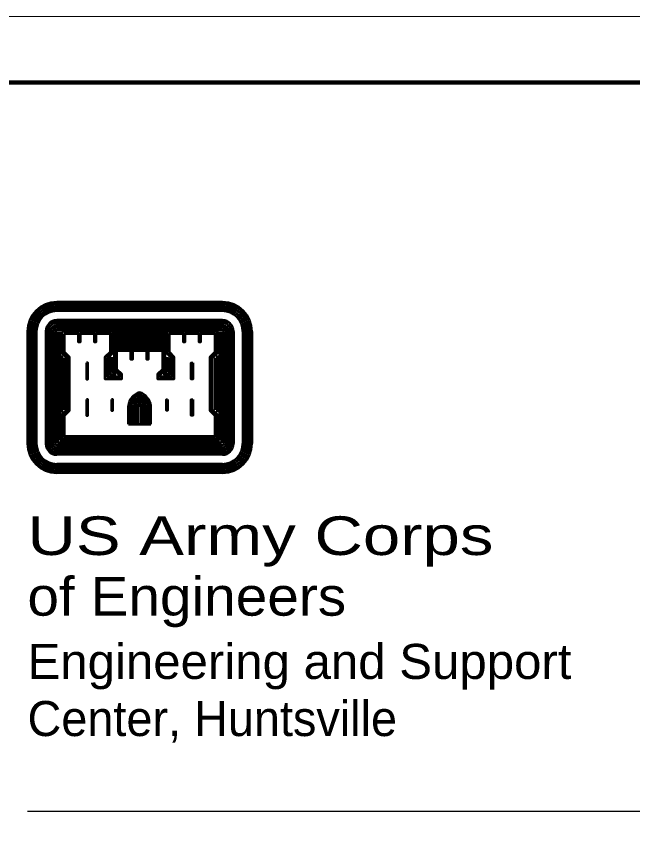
# Model space of a CAD drawing. Extents: x -153.1 to -120, y 360.9 to 384.2.
# Drawn here: x -149.62 to -145.22, y 378.39 to 384.24 of the extents above; entities that cross this region are included whole.
import ezdxf

# ---------------------------------------------------------------- set-up
doc = ezdxf.new("R2010")
doc.units = 0
doc.header["$LTSCALE"] = 0.039
doc.layers.add('1', color=7, linetype='Continuous', lineweight=80)
doc.layers.add('2', color=7, linetype='Continuous', lineweight=53)

msp = doc.modelspace()

# ---------------------------------------------------------------- linework, layer by layer
at = {"layer": '1', "lineweight": 25}
for p in [(-124.33602, 378.5668), (-126.54058, 378.5668)]:
    msp.add_line(p, (-149.54265, 378.5668), dxfattribs=at)
at = {"layer": '1', "lineweight": 13}
msp.add_lwpolyline([(-153.08523, 360.85466), (-119.97531, 360.85466), (-119.97531, 384.24028), (-153.08523, 384.24028)], close=True, dxfattribs=at)
msp.add_lwpolyline([(-153.08523, 360.85466), (-119.97531, 360.85466), (-119.97531, 384.24028), (-153.08523, 384.24028)], close=True, dxfattribs=at)
msp.add_lwpolyline([(-153.08523, 360.85466), (-119.97531, 360.85466), (-119.97531, 384.24028), (-153.08523, 384.24028)], close=True, dxfattribs=at)
at = {"layer": '1', "lineweight": 90}
msp.add_lwpolyline([(-152.02225, 383.76784), (-120.44775, 383.76784), (-120.44775, 361.32709)], dxfattribs=at)
msp.add_lwpolyline([(-152.02225, 383.76784), (-120.44775, 383.76784), (-120.44775, 361.32709)], dxfattribs=at)
msp.add_lwpolyline([(-152.02225, 383.76784), (-120.44775, 383.76784), (-120.44775, 361.32709)], dxfattribs=at)
at = {"layer": '2'}
for p, q in [((-148.14948, 382.20126), (-149.33242, 382.20126)), ((-148.14948, 382.20126), (-149.33242, 382.20126)), ((-148.14948, 382.20126), (-149.33242, 382.20126)), ((-148.14948, 382.18874), (-149.33242, 382.18874)), ((-148.14948, 382.18874), (-149.33242, 382.18874)), ((-148.14948, 382.18874), (-149.33242, 382.18874)), ((-148.14948, 382.17172), (-149.33242, 382.17172)), ((-148.14948, 382.17172), (-149.33242, 382.17172)), ((-148.14948, 382.17172), (-149.33242, 382.17172)), ((-148.14948, 382.15503), (-149.33242, 382.15503)), ((-148.14948, 382.15503), (-149.33242, 382.15503)), ((-148.14948, 382.15503), (-149.33242, 382.15503)), ((-148.14948, 382.13864), (-149.33242, 382.13864)), ((-148.14948, 382.13864), (-149.33242, 382.13864)), ((-148.14948, 382.13864), (-149.33242, 382.13864)), ((-148.14948, 382.07149), (-149.33242, 382.07149)), ((-148.14948, 382.07149), (-149.33242, 382.07149)), ((-148.14948, 382.07149), (-149.33242, 382.07149)), ((-148.14948, 382.05255), (-149.33242, 382.05255)), ((-148.14948, 382.05255), (-149.33242, 382.05255)), ((-148.14948, 382.05255), (-149.33242, 382.05255)), ((-148.14948, 382.03639), (-149.33242, 382.03639)), ((-148.14948, 382.03639), (-149.33242, 382.03639)), ((-148.14948, 382.03639), (-149.33242, 382.03639)), ((-148.14948, 382.01966), (-149.33242, 382.01966)), ((-148.14948, 382.01966), (-149.33242, 382.01966)), ((-148.14948, 382.01966), (-149.33242, 382.01966)), ((-149.54265, 381.99128), (-149.54265, 381.19178)), ((-149.54265, 381.99128), (-149.54265, 381.19178)), ((-149.54265, 381.99128), (-149.54265, 381.19178)), ((-149.53042, 381.99128), (-149.53042, 381.19178)), ((-149.53042, 381.99128), (-149.53042, 381.19178)), ((-149.51177, 381.99128), (-149.51177, 381.19178)), ((-149.51177, 381.99128), (-149.51177, 381.19178)), ((-149.49531, 381.99128), (-149.49531, 381.19178)), ((-149.49531, 381.99128), (-149.49531, 381.19178)), ((-149.47917, 381.99128), (-149.47917, 381.19178)), ((-149.47917, 381.99128), (-149.47917, 381.19178)), ((-149.4101, 381.99128), (-149.4101, 381.19178)), ((-149.4101, 381.99128), (-149.4101, 381.19178)), ((-149.4101, 381.99128), (-149.4101, 381.19178)), ((-149.39479, 381.99128), (-149.39479, 381.19178)), ((-149.39479, 381.99128), (-149.39479, 381.19178)), ((-149.39479, 381.99128), (-149.39479, 381.19178)), ((-149.37721, 381.99128), (-149.37721, 381.19178)), ((-149.37721, 381.99128), (-149.37721, 381.19178)), ((-149.37721, 381.99128), (-149.37721, 381.19178)), ((-149.35998, 381.99128), (-149.35998, 381.19178)), ((-149.35998, 381.99128), (-149.35998, 381.19178)), ((-149.35998, 381.99128), (-149.35998, 381.19178)), ((-149.34325, 381.99128), (-149.34325, 381.19178)), ((-149.34325, 381.99128), (-149.34325, 381.19178)), ((-149.34325, 381.99128), (-149.34325, 381.19178)), ((-148.14948, 382.00243), (-149.33242, 382.00243)), ((-148.14948, 382.00243), (-149.33242, 382.00243)), ((-148.14948, 382.00243), (-149.33242, 382.00243)), ((-149.32708, 381.99128), (-149.32708, 381.19791)), ((-149.32708, 381.99128), (-149.32708, 381.19791)), ((-149.30988, 381.99128), (-149.30988, 381.2152)), ((-149.30988, 381.99128), (-149.30988, 381.2152)), ((-148.92358, 381.98709), (-148.55933, 381.98709)), ((-148.92358, 381.98709), (-148.55933, 381.98709)), ((-148.92358, 381.97066), (-148.55933, 381.97066)), ((-148.92358, 381.97066), (-148.55933, 381.97066)), ((-148.92358, 381.95453), (-148.55933, 381.95453)), ((-148.92358, 381.95453), (-148.55933, 381.95453)), ((-148.17204, 381.99128), (-148.17204, 381.2152)), ((-148.17204, 381.99128), (-148.17204, 381.2152)), ((-148.15583, 381.99128), (-148.15583, 381.19791)), ((-148.15583, 381.99128), (-148.15583, 381.19791)), ((-148.13915, 381.99128), (-148.13915, 381.19178)), ((-148.13915, 381.99128), (-148.13915, 381.19178)), ((-148.13915, 381.99128), (-148.13915, 381.19178)), ((-148.12077, 381.99128), (-148.12077, 381.19178)), ((-148.12077, 381.99128), (-148.12077, 381.19178)), ((-148.12077, 381.99128), (-148.12077, 381.19178)), ((-148.10519, 381.99128), (-148.10519, 381.19178)), ((-148.10519, 381.99128), (-148.10519, 381.19178)), ((-148.10519, 381.99128), (-148.10519, 381.19178)), ((-148.08904, 381.99128), (-148.08904, 381.19178)), ((-148.08904, 381.99128), (-148.08904, 381.19178)), ((-148.08904, 381.99128), (-148.08904, 381.19178)), ((-148.07067, 381.99128), (-148.07067, 381.19178)), ((-148.07067, 381.99128), (-148.07067, 381.19178)), ((-148.07067, 381.99128), (-148.07067, 381.19178)), ((-148.00381, 381.99128), (-148.00381, 381.19178)), ((-148.00381, 381.99128), (-148.00381, 381.19178)), ((-148.00381, 381.99128), (-148.00381, 381.19178)), ((-147.98656, 381.99128), (-147.98656, 381.19178)), ((-147.98656, 381.99128), (-147.98656, 381.19178)), ((-147.98656, 381.99128), (-147.98656, 381.19178)), ((-147.969, 381.99128), (-147.969, 381.19178)), ((-147.969, 381.99128), (-147.969, 381.19178)), ((-147.95288, 381.99128), (-147.95288, 381.19178)), ((-147.95288, 381.99128), (-147.95288, 381.19178)), ((-147.94033, 381.99128), (-147.94033, 381.19178)), ((-147.94033, 381.99128), (-147.94033, 381.19178)), ((-147.94033, 381.99128), (-147.94033, 381.19178)), ((-148.92358, 381.93699), (-148.55933, 381.93699)), ((-148.92358, 381.93699), (-148.55933, 381.93699)), ((-148.92358, 381.92053), (-148.55933, 381.92053)), ((-148.92358, 381.92053), (-148.55933, 381.92053)), ((-148.92358, 381.90355), (-148.55933, 381.90355)), ((-148.92358, 381.90355), (-148.55933, 381.90355)), ((-148.92358, 381.88547), (-148.55933, 381.88547)), ((-148.92358, 381.88547), (-148.55933, 381.88547)), ((-149.29704, 381.82084), (-149.29704, 381.41234)), ((-149.29704, 381.82084), (-149.29704, 381.41234)), ((-149.27867, 381.80416), (-149.27867, 381.43186)), ((-149.27867, 381.80416), (-149.27867, 381.43186)), ((-148.2021, 381.80416), (-148.2021, 381.43186)), ((-148.2021, 381.80416), (-148.2021, 381.43186)), ((-148.18708, 381.81949), (-148.18708, 381.41484)), ((-148.18708, 381.81949), (-148.18708, 381.41484)), ((-148.82004, 381.33074), (-148.82004, 381.46109)), ((-148.82004, 381.33074), (-148.82004, 381.46109)), ((-148.80335, 381.33074), (-148.80335, 381.46109)), ((-148.80335, 381.33074), (-148.80335, 381.46109)), ((-148.78604, 381.33074), (-148.78604, 381.46109)), ((-148.78604, 381.33074), (-148.78604, 381.46109)), ((-148.76994, 381.33074), (-148.76994, 381.46109)), ((-148.76994, 381.33074), (-148.76994, 381.46109)), ((-148.75098, 381.33074), (-148.75098, 381.46109)), ((-148.75098, 381.33074), (-148.75098, 381.46109)), ((-148.72977, 381.33074), (-148.72977, 381.46109)), ((-148.72977, 381.33074), (-148.72977, 381.46109)), ((-148.71337, 381.33074), (-148.71337, 381.46109)), ((-148.71337, 381.33074), (-148.71337, 381.46109)), ((-148.69583, 381.33074), (-148.69583, 381.46109)), ((-148.69583, 381.33074), (-148.69583, 381.46109)), ((-148.67967, 381.33074), (-148.67967, 381.46109)), ((-148.67967, 381.33074), (-148.67967, 381.46109)), ((-148.6621, 381.33074), (-148.6621, 381.46109)), ((-148.6621, 381.33074), (-148.6621, 381.46109)), ((-148.82004, 381.33074), (-148.6621, 381.33074)), ((-148.82004, 381.33074), (-148.6621, 381.33074)), ((-148.15583, 381.19791), (-149.32708, 381.19791)), ((-148.15583, 381.19791), (-149.32708, 381.19791)), ((-148.17204, 381.2152), (-149.30988, 381.2152)), ((-148.17204, 381.2152), (-149.30988, 381.2152)), ((-148.14948, 381.18039), (-149.33242, 381.18039)), ((-148.14948, 381.18039), (-149.33242, 381.18039)), ((-148.14948, 381.18039), (-149.33242, 381.18039)), ((-148.14948, 381.16424), (-149.33242, 381.16424)), ((-148.14948, 381.16424), (-149.33242, 381.16424)), ((-148.14948, 381.16424), (-149.33242, 381.16424)), ((-148.14948, 381.14668), (-149.33242, 381.14668)), ((-148.14948, 381.14668), (-149.33242, 381.14668)), ((-148.14948, 381.14668), (-149.33242, 381.14668)), ((-148.14948, 381.12999), (-149.33242, 381.12999)), ((-148.14948, 381.12999), (-149.33242, 381.12999)), ((-148.14948, 381.12999), (-149.33242, 381.12999)), ((-148.14948, 381.11272), (-149.33242, 381.11272)), ((-148.14948, 381.11272), (-149.33242, 381.11272)), ((-148.14948, 381.11272), (-149.33242, 381.11272)), ((-148.14948, 381.04476), (-149.33242, 381.04476)), ((-148.14948, 381.04476), (-149.33242, 381.04476)), ((-148.14948, 381.02836), (-149.33242, 381.02836)), ((-148.14948, 381.02836), (-149.33242, 381.02836)), ((-148.14948, 381.01249), (-149.33242, 381.01249)), ((-148.14948, 381.01249), (-149.33242, 381.01249)), ((-148.14948, 380.99466), (-149.33242, 380.99466)), ((-148.14948, 380.99466), (-149.33242, 380.99466)), ((-148.14948, 380.98239), (-149.33242, 380.98239)), ((-148.14948, 380.98239), (-149.33242, 380.98239)), ((-148.14948, 380.98239), (-149.33242, 380.98239))]:
    msp.add_line(p, q, dxfattribs=at)
for points in [[(-149.29704, 381.99128), (-149.29704, 381.83926), (-149.26221, 381.80416), (-149.26221, 381.43186), (-149.29704, 381.39676), (-149.29704, 381.22772), (-148.18537, 381.22772), (-148.18537, 381.39676), (-148.22048, 381.43186), (-148.22048, 381.80416), (-148.18537, 381.83926), (-148.18537, 381.99128), (-148.33133, 381.99128), (-148.44606, 381.99128), (-148.54937, 381.99128), (-148.54937, 381.83926), (-148.51288, 381.80416), (-148.51288, 381.66911), (-148.59392, 381.66911), (-148.59392, 381.68166), (-148.55933, 381.71643), (-148.55933, 381.86849), (-148.70669, 381.86849), (-148.81865, 381.86849), (-148.92358, 381.86849), (-148.92358, 381.71643), (-148.88852, 381.68166), (-148.88852, 381.66911), (-148.96787, 381.66911), (-148.96787, 381.80416), (-148.93281, 381.83926), (-148.93281, 381.99128), (-149.08181, 381.99128), (-149.19427, 381.99128)], [(-149.29704, 381.99128), (-149.29704, 381.83926), (-149.26221, 381.80416), (-149.26221, 381.43186), (-149.29704, 381.39676), (-149.29704, 381.22772), (-148.18537, 381.22772), (-148.18537, 381.39676), (-148.22048, 381.43186), (-148.22048, 381.80416), (-148.18537, 381.83926), (-148.18537, 381.99128), (-148.33133, 381.99128), (-148.44606, 381.99128), (-148.54937, 381.99128), (-148.54937, 381.83926), (-148.51288, 381.80416), (-148.51288, 381.66911), (-148.59392, 381.66911), (-148.59392, 381.68166), (-148.55933, 381.71643), (-148.55933, 381.86849), (-148.70669, 381.86849), (-148.81865, 381.86849), (-148.92358, 381.86849), (-148.92358, 381.71643), (-148.88852, 381.68166), (-148.88852, 381.66911), (-148.96787, 381.66911), (-148.96787, 381.80416), (-148.93281, 381.83926), (-148.93281, 381.99128), (-149.08181, 381.99128), (-149.19427, 381.99128)], [(-149.29704, 381.99128), (-149.29704, 381.83926), (-149.26221, 381.80416), (-149.26221, 381.43186), (-149.29704, 381.39676), (-149.29704, 381.22772), (-148.18537, 381.22772), (-148.18537, 381.39676), (-148.22048, 381.43186), (-148.22048, 381.80416), (-148.18537, 381.83926), (-148.18537, 381.99128), (-148.33133, 381.99128), (-148.44606, 381.99128), (-148.54937, 381.99128), (-148.54937, 381.83926), (-148.51288, 381.80416), (-148.51288, 381.66911), (-148.59392, 381.66911), (-148.59392, 381.68166), (-148.55933, 381.71643), (-148.55933, 381.86849), (-148.70669, 381.86849), (-148.81865, 381.86849), (-148.92358, 381.86849), (-148.92358, 381.71643), (-148.88852, 381.68166), (-148.88852, 381.66911), (-148.96787, 381.66911), (-148.96787, 381.80416), (-148.93281, 381.83926), (-148.93281, 381.99128), (-149.08181, 381.99128), (-149.19427, 381.99128)], [(-149.27977, 381.97459), (-149.27977, 381.84536), (-149.24552, 381.81084), (-149.24552, 381.42572), (-149.27977, 381.39061), (-149.27977, 381.24526), (-148.2021, 381.24526), (-148.2021, 381.39061), (-148.23692, 381.42572), (-148.23692, 381.81084), (-148.2021, 381.84536), (-148.2021, 381.97459), (-148.30569, 381.97459), (-148.30569, 381.91443), (-148.31571, 381.91443), (-148.31571, 381.97459), (-148.41904, 381.97459), (-148.41904, 381.91443), (-148.42767, 381.91443), (-148.42767, 381.97459), (-148.53044, 381.97459), (-148.53044, 381.84536), (-148.49783, 381.81084), (-148.49783, 381.65155), (-148.6106, 381.65155), (-148.6106, 381.68916), (-148.57635, 381.72311), (-148.57635, 381.85345), (-148.67967, 381.85345), (-148.67967, 381.79159), (-148.68971, 381.79159), (-148.68971, 381.85345), (-148.79331, 381.85345), (-148.79331, 381.79159), (-148.80335, 381.79159), (-148.80335, 381.85345), (-148.90608, 381.85345), (-148.90608, 381.72311), (-148.87017, 381.68916), (-148.87017, 381.65155), (-148.98654, 381.65155), (-148.98654, 381.81084), (-148.95033, 381.84536), (-148.95033, 381.97459), (-149.0531, 381.97459), (-149.0531, 381.91443), (-149.06398, 381.91443), (-149.06398, 381.97459), (-149.16698, 381.97459), (-149.16698, 381.91443), (-149.17675, 381.91443), (-149.17675, 381.97459)], [(-149.27977, 381.97459), (-149.27977, 381.84536), (-149.24552, 381.81084), (-149.24552, 381.42572), (-149.27977, 381.39061), (-149.27977, 381.24526), (-148.2021, 381.24526), (-148.2021, 381.39061), (-148.23692, 381.42572), (-148.23692, 381.81084), (-148.2021, 381.84536), (-148.2021, 381.97459), (-148.30569, 381.97459), (-148.30569, 381.91443), (-148.31571, 381.91443), (-148.31571, 381.97459), (-148.41904, 381.97459), (-148.41904, 381.91443), (-148.42767, 381.91443), (-148.42767, 381.97459), (-148.53044, 381.97459), (-148.53044, 381.84536), (-148.49783, 381.81084), (-148.49783, 381.65155), (-148.6106, 381.65155), (-148.6106, 381.68916), (-148.57635, 381.72311), (-148.57635, 381.85345), (-148.67967, 381.85345), (-148.67967, 381.79159), (-148.68971, 381.79159), (-148.68971, 381.85345), (-148.79331, 381.85345), (-148.79331, 381.79159), (-148.80335, 381.79159), (-148.80335, 381.85345), (-148.90608, 381.85345), (-148.90608, 381.72311), (-148.87017, 381.68916), (-148.87017, 381.65155), (-148.98654, 381.65155), (-148.98654, 381.81084), (-148.95033, 381.84536), (-148.95033, 381.97459), (-149.0531, 381.97459), (-149.0531, 381.91443), (-149.06398, 381.91443), (-149.06398, 381.97459), (-149.16698, 381.97459), (-149.16698, 381.91443), (-149.17675, 381.91443), (-149.17675, 381.97459)], [(-149.27977, 381.97459), (-149.27977, 381.84536), (-149.24552, 381.81084), (-149.24552, 381.42572), (-149.27977, 381.39061), (-149.27977, 381.24526), (-148.2021, 381.24526), (-148.2021, 381.39061), (-148.23692, 381.42572), (-148.23692, 381.81084), (-148.2021, 381.84536), (-148.2021, 381.97459), (-148.30569, 381.97459), (-148.30569, 381.91443), (-148.31571, 381.91443), (-148.31571, 381.97459), (-148.41904, 381.97459), (-148.41904, 381.91443), (-148.42767, 381.91443), (-148.42767, 381.97459), (-148.53044, 381.97459), (-148.53044, 381.84536), (-148.49783, 381.81084), (-148.49783, 381.65155), (-148.6106, 381.65155), (-148.6106, 381.68916), (-148.57635, 381.72311), (-148.57635, 381.85345), (-148.67967, 381.85345), (-148.67967, 381.79159), (-148.68971, 381.79159), (-148.68971, 381.85345), (-148.79331, 381.85345), (-148.79331, 381.79159), (-148.80335, 381.79159), (-148.80335, 381.85345), (-148.90608, 381.85345), (-148.90608, 381.72311), (-148.87017, 381.68916), (-148.87017, 381.65155), (-148.98654, 381.65155), (-148.98654, 381.81084), (-148.95033, 381.84536), (-148.95033, 381.97459), (-149.0531, 381.97459), (-149.0531, 381.91443), (-149.06398, 381.91443), (-149.06398, 381.97459), (-149.16698, 381.97459), (-149.16698, 381.91443), (-149.17675, 381.91443), (-149.17675, 381.97459)], [(-149.12023, 381.76684), (-149.12023, 381.65155), (-149.11019, 381.65155), (-149.11019, 381.76684)], [(-149.12023, 381.76684), (-149.12023, 381.65155), (-149.11019, 381.65155), (-149.11019, 381.76684)], [(-148.36225, 381.76684), (-148.36225, 381.65155), (-148.3725, 381.65155), (-148.3725, 381.76684)], [(-148.36225, 381.76684), (-148.36225, 381.65155), (-148.3725, 381.65155), (-148.3725, 381.76684)], [(-149.12023, 381.50507), (-149.12023, 381.39172), (-149.11019, 381.39172), (-149.11019, 381.50507)], [(-149.12023, 381.50507), (-149.12023, 381.39172), (-149.11019, 381.39172), (-149.11019, 381.50507)], [(-148.94225, 381.50507), (-148.94225, 381.42686), (-148.9314, 381.42686), (-148.9314, 381.50507)], [(-148.94225, 381.50507), (-148.94225, 381.42686), (-148.9314, 381.42686), (-148.9314, 381.50507)], [(-148.54129, 381.50507), (-148.54129, 381.42686), (-148.55044, 381.42686), (-148.55044, 381.50507)], [(-148.54129, 381.50507), (-148.54129, 381.42686), (-148.55044, 381.42686), (-148.55044, 381.50507)], [(-148.36225, 381.50507), (-148.36225, 381.39172), (-148.3725, 381.39172), (-148.3725, 381.50507)], [(-148.36225, 381.50507), (-148.36225, 381.39172), (-148.3725, 381.39172), (-148.3725, 381.50507)]]:
    msp.add_lwpolyline(points, close=True, dxfattribs=at)
for points in [[(-148.94119, 381.80666), (-148.95144, 381.79666), (-148.95144, 381.68555), (-148.91527, 381.68555), (-148.93975, 381.71003), (-148.93975, 381.8078)], [(-148.94119, 381.80666), (-148.95144, 381.79666), (-148.95144, 381.68555), (-148.91527, 381.68555), (-148.93975, 381.71003), (-148.93975, 381.8078)], [(-148.54129, 381.80666), (-148.53044, 381.79666), (-148.53044, 381.68555), (-148.5655, 381.68555), (-148.54265, 381.71003), (-148.54265, 381.8078)], [(-148.54129, 381.80666), (-148.53044, 381.79666), (-148.53044, 381.68555), (-148.5655, 381.68555), (-148.54265, 381.71003), (-148.54265, 381.8078)]]:
    msp.add_lwpolyline(points, dxfattribs=at)
for centre, radius, start, end in [((-149.3329, 381.99206), 0.20886, 90, 180), ((-149.3329, 381.99206), 0.20886, 90, 180), ((-149.3329, 381.99206), 0.20886, 90, 180), ((-149.3329, 381.99206), 0.19678, 90, 180), ((-149.3329, 381.99206), 0.19678, 90, 180), ((-148.14935, 381.99206), 0.20886, 0, 90), ((-148.14935, 381.99206), 0.20886, 0, 90), ((-148.14935, 381.99206), 0.20886, 0, 90), ((-148.14935, 381.99206), 0.19678, 0, 90), ((-148.14935, 381.99206), 0.19678, 0, 90), ((-149.3329, 381.99206), 0.17985, 90, 180), ((-149.3329, 381.99206), 0.17985, 90, 180), ((-149.3329, 381.99206), 0.16293, 90, 180), ((-149.3329, 381.99206), 0.16293, 90, 180), ((-149.3329, 381.99206), 0.14601, 90, 180), ((-149.3329, 381.99206), 0.14601, 90, 180), ((-148.14935, 381.99206), 0.17985, 0, 90), ((-148.14935, 381.99206), 0.17985, 0, 90), ((-148.14935, 381.99206), 0.16293, 0, 90), ((-148.14935, 381.99206), 0.16293, 0, 90), ((-148.14935, 381.99206), 0.14601, 0, 90), ((-148.14935, 381.99206), 0.14601, 0, 90), ((-149.3329, 381.99206), 0.07832, 90, 180), ((-149.3329, 381.99206), 0.07832, 90, 180), ((-149.3329, 381.99206), 0.07832, 90, 180), ((-148.14935, 381.99206), 0.07832, 0, 90), ((-148.14935, 381.99206), 0.07832, 0, 90), ((-148.14935, 381.99206), 0.07832, 0, 90), ((-149.3329, 381.99206), 0.0614, 90, 180), ((-149.3329, 381.99206), 0.0614, 90, 180), ((-149.3329, 381.99206), 0.0614, 90, 180), ((-149.3329, 381.99206), 0.04448, 90, 180), ((-149.3329, 381.99206), 0.04448, 90, 180), ((-149.3329, 381.99206), 0.04448, 90, 180), ((-149.3329, 381.99206), 0.02756, 90, 180), ((-149.3329, 381.99206), 0.02756, 90, 180), ((-149.3329, 381.99206), 0.02756, 90, 180), ((-148.14935, 381.99206), 0.0614, 0, 90), ((-148.14935, 381.99206), 0.0614, 0, 90), ((-148.14935, 381.99206), 0.0614, 0, 90), ((-148.14935, 381.99206), 0.04448, 0, 90), ((-148.14935, 381.99206), 0.04448, 0, 90), ((-148.14935, 381.99206), 0.04448, 0, 90), ((-148.14935, 381.99206), 0.02756, 0, 90), ((-148.14935, 381.99206), 0.02756, 0, 90), ((-148.14935, 381.99206), 0.02756, 0, 90), ((-149.3329, 381.99206), 0.01064, 90, 180), ((-149.3329, 381.99206), 0.01064, 90, 180), ((-149.3329, 381.99206), 0.01064, 90, 180), ((-148.14935, 381.99206), 0.01064, 0, 90), ((-148.14935, 381.99206), 0.01064, 0, 90), ((-148.14935, 381.99206), 0.01064, 0, 90), ((-148.71197, 381.45259), 0.10826, 105.66806, 176.05748), ((-148.71197, 381.45259), 0.10826, 105.66806, 176.05748), ((-148.71197, 381.45259), 0.09134, 103.46979, 176.05748), ((-148.71197, 381.45259), 0.09134, 103.46979, 176.05748), ((-148.77029, 381.45259), 0.09134, 3.94252, 76.53021), ((-148.77029, 381.45259), 0.09134, 3.94252, 76.53021), ((-148.77029, 381.45259), 0.10826, 3.94252, 74.39486), ((-148.77029, 381.45259), 0.10826, 3.94252, 74.39486), ((-148.71197, 381.45259), 0.07442, 103.46979, 176.05748), ((-148.71197, 381.45259), 0.07442, 103.46979, 176.05748), ((-148.71197, 381.45259), 0.0575, 103.46979, 176.05748), ((-148.71197, 381.45259), 0.0575, 103.46979, 176.05748), ((-148.77029, 381.45259), 0.04057, 3.94252, 76.53021), ((-148.77029, 381.45259), 0.04057, 3.94252, 76.53021), ((-148.77029, 381.45259), 0.0575, 3.94252, 76.53021), ((-148.77029, 381.45259), 0.0575, 3.94252, 76.53021), ((-148.77029, 381.45259), 0.07442, 3.94253, 76.53022), ((-148.77029, 381.45259), 0.07442, 3.94253, 76.53022), ((-148.71197, 381.45259), 0.04057, 103.46979, 176.05748), ((-148.71197, 381.45259), 0.04057, 103.46979, 176.05748), ((-149.3329, 381.19142), 0.20886, 180, 270), ((-149.3329, 381.19142), 0.20886, 180, 270), ((-149.3329, 381.19142), 0.20886, 180, 270), ((-149.3329, 381.19142), 0.19678, 180, 270), ((-149.3329, 381.19142), 0.19678, 180, 270), ((-149.3329, 381.19142), 0.17985, 180, 270), ((-149.3329, 381.19142), 0.17985, 180, 270), ((-149.3329, 381.19142), 0.16293, 180, 270), ((-149.3329, 381.19142), 0.16293, 180, 270), ((-149.3329, 381.19142), 0.14601, 180, 270), ((-149.3329, 381.19142), 0.14601, 180, 270), ((-149.3329, 381.19142), 0.07832, 180, 270), ((-149.3329, 381.19142), 0.07832, 180, 270), ((-149.3329, 381.19142), 0.07832, 180, 270), ((-149.3329, 381.19142), 0.0614, 180, 270), ((-149.3329, 381.19142), 0.0614, 180, 270), ((-149.3329, 381.19142), 0.0614, 180, 270), ((-149.3329, 381.19142), 0.04448, 180, 270), ((-149.3329, 381.19142), 0.04448, 180, 270), ((-149.3329, 381.19142), 0.04448, 180, 270), ((-149.3329, 381.19142), 0.02756, 180, 270), ((-149.3329, 381.19142), 0.02756, 180, 270), ((-149.3329, 381.19142), 0.02756, 180, 270), ((-149.3329, 381.19142), 0.01064, 180, 270), ((-149.3329, 381.19142), 0.01064, 180, 270), ((-149.3329, 381.19142), 0.01064, 180, 270), ((-148.14935, 381.19142), 0.20886, 270, 0), ((-148.14935, 381.19142), 0.07832, 270, 0), ((-148.14935, 381.19142), 0.0614, 270, 0), ((-148.14935, 381.19142), 0.04448, 270, 0), ((-148.14935, 381.19142), 0.02756, 270, 0), ((-148.14935, 381.19142), 0.01064, 270, 0), ((-148.14935, 381.19142), 0.14601, 270, 360), ((-148.14935, 381.19142), 0.16293, 270, 360), ((-148.14935, 381.19142), 0.17985, 270, 360), ((-148.14935, 381.19142), 0.19678, 270, 360), ((-148.14935, 381.19142), 0.20886, 270, 0), ((-148.14935, 381.19142), 0.07832, 270, 0), ((-148.14935, 381.19142), 0.0614, 270, 0), ((-148.14935, 381.19142), 0.04448, 270, 0), ((-148.14935, 381.19142), 0.02756, 270, 0), ((-148.14935, 381.19142), 0.01064, 270, 0), ((-148.14935, 381.19142), 0.14601, 270, 360), ((-148.14935, 381.19142), 0.16293, 270, 360), ((-148.14935, 381.19142), 0.17985, 270, 360), ((-148.14935, 381.19142), 0.19678, 270, 360), ((-148.14935, 381.19142), 0.20886, 270, 0), ((-148.14935, 381.19142), 0.07832, 270, 0), ((-148.14935, 381.19142), 0.0614, 270, 0), ((-148.14935, 381.19142), 0.04448, 270, 0), ((-148.14935, 381.19142), 0.02756, 270, 0), ((-148.14935, 381.19142), 0.01064, 270, 0), ((-148.14935, 381.19142), 0.14601, 270, 360), ((-148.14935, 381.19142), 0.16293, 270, 360), ((-148.14935, 381.19142), 0.17985, 270, 360), ((-148.14935, 381.19142), 0.19678, 270, 360)]:
    msp.add_arc(centre, radius, start, end, dxfattribs=at)

# ---------------------------------------------------------------- texts
for s, height, width, p in [('US Army Corps', 0.2756, 1.3, (-149.54265, 380.39649)), ('US Army Corps', 0.2756, 1.3, (-149.54265, 380.39649)), ('of Engineers', 0.2756, 1.1, (-149.54265, 379.96341)), ('of Engineers', 0.2756, 1.1, (-149.54265, 379.96341)), ('Engineering and Support', 0.25, 1.05, (-149.54171, 379.51197)), ('Engineering and Support', 0.25, 1.05, (-149.54171, 379.51197))]:
    msp.add_text(s, height=height, dxfattribs=dict(at, width=width)).set_placement(p)
msp.add_text('Center, Huntsville', height=0.25, dxfattribs=at).set_placement((-149.54171, 379.10449))
msp.add_text('Center, Huntsville', height=0.25, dxfattribs=at).set_placement((-149.54171, 379.10449))

doc.saveas('drawing.dxf')
